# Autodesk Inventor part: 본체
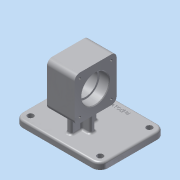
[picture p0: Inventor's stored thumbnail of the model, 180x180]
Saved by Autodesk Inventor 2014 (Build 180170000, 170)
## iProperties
Created: 2020-11
Part Number: 본체
Material: 알루미늄 6061
Document SubType Name: Modeling
Designer: kh
Density: 2.71 g/cm^3
Appearance: 알루미늄 - 평지
Mass: 711.128 g
Surface Area: 552.419 cm^2
Volume: 262.409 cm^3
Author: kh
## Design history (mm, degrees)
sketch "스케치1"
  geometry: L1 (-65, -49.5)-(65, -49.5); L2 (65, -49.5)-(65, 49.5); L3 (65, 49.5)-(-65, 49.5); L4 (-65, 49.5)-(-65, -49.5); L5 (-65, -49.5)-(65, 49.5); L6 (65, -49.5)-(-65, 49.5); 1 further point
  constraints: 12 end point, 2 midpoint, 2 parallel, 1 horizontal, 1 perpendicular
  dimensions: "d0" = 130 distance of L2.end L3.end; "d1" = 99 distance of L1.end L2.end
extrude "돌출1" new body sketch "스케치1" distance "d2" = 10; taper "d3" = 0 deg
fillet "모깎기1" dims "d4" = 12
sketch "스케치2"
  geometry: L1 (-53, -49.5)-(53, -49.5) reference; L2 (65, -37.5)-(65, 37.5) reference; L3 (53, 49.5)-(-53, 49.5) reference; L4 (4, -32.5)-(-4, -32.5); L5 (-4, -32.5)-(-4, 7.5); L6 (-4, 7.5)-(4, 7.5); L7 (4, 7.5)-(4, -32.5); L8 (0, -32.5)-(0, 7.5); L9 (17, -16.5)-(-17, -16.5); L10 (-17, -16.5)-(-17, -8.5); L11 (-17, -8.5)-(17, -8.5); L12 (17, -8.5)-(17, -16.5); L13 (-4, -12.5)-(4, -12.5); L14 (-17, -12.5)-(17, -12.5); 3 further points
  constraints: 22 end point, 8 midpoint, 4 parallel, 2 horizontal, 2 perpendicular, 1 vertical alignment
  dimensions: "d6" = 8 distance of L5.end L6.end; "d8" = 65 distance between parallel lines of L2 L8; "d10" = 34 distance of L9.start L9.end; "d11" = 8 distance of L11.end L9.start; "d12" = 40 distance of L6.end L4.start; "d13" = 62 distance between parallel lines of L13 L3; "d14" = 62 distance between parallel lines of L14 L3
extrude "돌출2" join sketch "스케치2" distance "d15" = 60; taper "d16" = 0 deg
sketch "스케치3"
  geometry: L1 (-16.5, 70)-(-32.5, 70) reference; L2 (7.5, 70)-(-8.5, 70) reference; L3 (-8.5, 70)-(-16.5, 70) reference; L4 (-44.5, 36.5)-(19.5, 36.5); L5 (19.5, 36.5)-(19.5, 103.5); L6 (19.5, 103.5)-(-44.5, 103.5); L7 (-44.5, 103.5)-(-44.5, 36.5); L8 (-44.5, 36.5)-(19.5, 103.5); L9 (19.5, 36.5)-(-44.5, 103.5); 2 further points
  constraints: 12 end point, 3 midpoint, 2 parallel, 1 horizontal, 1 perpendicular
  dimensions: "d17" = 67 distance of L4.end L5.end; "d18" = 64 distance of L5.end L6.end
extrude "돌출3" join sketch "스케치3" stored distance "d19" = 42; taper "d20" = 0 deg
fillet "모깎기2" dims "d21" = 8
sketch "스케치4"
  geometry: L1 (-44.5, 19.5)-(-95.5, 19.5) reference; L2 (-103.5, 11.5)-(-103.5, -36.5) reference; L3 (-95.5, -44.5)-(-44.5, -44.5) reference; L4 (-36.5, -36.5)-(-36.5, 11.5) reference; L5 (-103.5, -12.5)-(-36.5, -12.5); L6 (-70, 19.5)-(-70, -44.5); C1 r 21 at (-70, -12.5); 1 further point
  constraints: 5 midpoint, 4 end point, 1 centre point
  dimensions: "d22" = 42 diameter of C1
extrude "돌출4" cut sketch "스케치4" distance "d23" = 15; taper "d24" = 0 deg
sketch "스케치5"
  geometry: C1 r 21 at (0, 0) reference; C2 r 18 at (0, 0); 1 further point
  constraints: 1 centre point, 1 coincident
  dimensions: "d25" = 36 diameter of C2
extrude "돌출5" cut sketch "스케치5" distance "d26" = 15; taper "d27" = 0 deg
sketch "스케치6"
  geometry: A1 r 8 centre (-44.5, 11.5) between (-36.5, 11.5) and (-44.5, 19.5) reference; A2 r 8 centre (-95.5, 11.5) between (-95.5, 19.5) and (-103.5, 11.5) reference; A3 r 8 centre (-95.5, -36.5) between (-103.5, -36.5) and (-95.5, -44.5) reference; A4 r 8 centre (-44.5, -36.5) between (-44.5, -44.5) and (-36.5, -36.5) reference; 1 further point
hole "구멍1" sketch "스케치6" at (-95.5, -36.5), (-95.5, 11.5), (-44.5, -36.5), (-44.5, 11.5) diameter "d28" = 3.242; stored, may be unused: countersink angle "d32" = 90 deg, drill point angle "d34" = 118 deg; dims "d29" = 8, "d30" = 4, "d31" = 2, "d33" = 10
sketch "스케치7"
  geometry: A1 r 12 centre (-53, -37.5) between (-65, -37.5) and (-53, -49.5) reference; A2 r 12 centre (53, -37.5) between (53, -49.5) and (65, -37.5) reference; A3 r 12 centre (53, 37.5) between (65, 37.5) and (53, 49.5) reference; A4 r 12 centre (-53, 37.5) between (-53, 49.5) and (-65, 37.5) reference; 1 further point
hole "구멍2" sketch "스케치7" at (53, 37.5), (53, -37.5), (-53, -37.5), (-53, 37.5) diameter "d35" = 9; stored, may be unused: countersink angle "d39" = 90 deg, drill point angle "d41" = 0 deg; dims "d36" = 8, "d37" = 4, "d38" = 2, "d40" = 10
fillet "모깎기3" dims "d42" = 3
fillet "모깎기4" dims "d43" = 3
fillet "모깎기5" dims "d44" = 3
fillet "모깎기6" dims "d45" = 0.3
node "작업 평면1"
sketch "스케치8"
  geometry: L1 (53, 49.5)-(-53, 49.5) reference; L2 (-65, 37.5)-(-65, -37.5) reference; L3 (65, -37.5)-(65, 37.5) reference; 2 further points
  constraints: 1 other
  dimensions: "d47" = 10 distance from line of L1 point (0, 39.5); "d48" = 65 distance from line of L3 point (0, 39.5)
feature "엠보싱1" sketch "스케치8" dims "d0" = 130, "d1" = 99, "d6" = 8, "d8" = 65, "d12" = 40, "d13" = 62, "d49" = 0.5, "d50" = 0
chamfer "모따기1" distance "d51" = 1; stored, may be unused: second distance "d52" = 2, angle "d53" = 45 deg
node "솔리드1"
mirror "대칭1"
mirror "대칭2"
